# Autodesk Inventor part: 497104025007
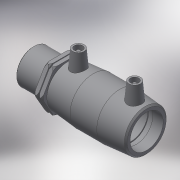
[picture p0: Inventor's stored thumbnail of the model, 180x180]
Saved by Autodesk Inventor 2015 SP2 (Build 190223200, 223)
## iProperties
Created: 2017-06
Part Number: 497104025007
Material: Generic
Description: PLASSON PE MALE TRANSITION COUPLER 25-3/4"
Document SubType Name: Modeling
Designer: KIM
Mass: 55.0731 g
Surface Area: 148.067 cm^2
Volume: 55.0731 cm^3
Density: 1 g/cm^3
Appearance: Default
Author: KIM
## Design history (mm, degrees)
derived "497104.ipt"
feature "Solid1::497104.ipt"
tag "TaggingFeature1"
body "Solid1"
other parameters: "d0" = 82, "d1" = 25, "d2" = 36, "d4" = 27.33333, "d5" = 32.4, "d6" = 23.75, "d7" = 25, "d8" = 168 deg, "d10" = 16, "d11" = 5.33333, "d29" = 37, "d30" = 14, "d31" = 28.7, "d34" = 5 deg, "d41" = 4, "d42" = 14, "d43" = 0, "d48" = 3, "d49" = 0, "d57" = 18, "d58" = 26.441, "d59" = 21.1528, "d60" = 27.9, "d61" = 37.0174, "d62" = 0.52882, "d65" = 1.08, "d70" = 0.1, "d71" = 31, "d72" = 7.75, "d73" = 16, "d75" = 0, "d76" = 0.775, "d77" = 3.4875, "d78" = 37.0174, "d_" = 25, "L_" = 113, "D_1" = 36, "A_" = 37, "d_2" = 12, "L_1" = 31, "D_" = 18, "R_" = 26.441
